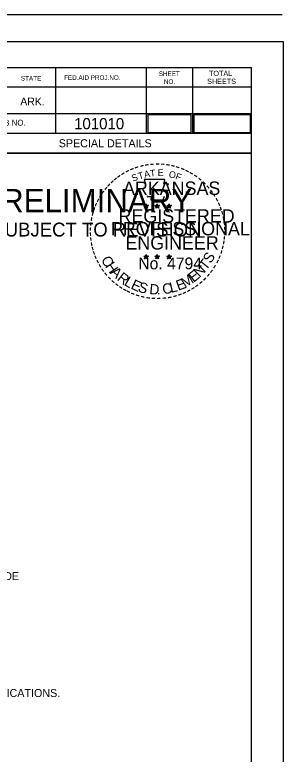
# Model space of a CAD drawing. Extents: x 3575 to 11445, y 9479 to 13278.
# Drawn here: x 5513 to 5714, y 10553 to 11106 of the extents above; entities that cross this region are included whole.
import ezdxf

# ---------------------------------------------------------------- set-up
doc = ezdxf.new("R2010")
doc.units = 0
for name, color, linetype in [('_Drafting 1', 7, 'Continuous'), ('Page Number', 7, 'Continuous'), ('R_NoPlot', 7, 'Continuous'), ('STAMP_PE_CRAFTON-SIGNATURE', 7, 'Continuous'), ('STAMP_PE_FOSTER-SIGNATURE', 7, 'Continuous'), ('STAMP_PE_SEAL-INFO', 7, 'Continuous'), ('STAMP_PE_TAEGTMEYER', 7, 'Continuous'), ('STAMP_PRELIMINARY', 7, 'Continuous'), ('Total_Pages', 7, 'Continuous')]:
    doc.layers.add(name, color=color, linetype=linetype)

msp = doc.modelspace()

# ---------------------------------------------------------------- linework, layer by layer
at = {"layer": '_Drafting 1'}
msp.add_lwpolyline([(4109.53, 11066.7), (4109.53, 10039.4), (5690.43, 10039.4), (5690.43, 11002.7), (5474.93, 11002.7), (5474.93, 11001.26), (5458.74, 11001.26), (5458.74, 11017.3), (5279.13, 11017.3), (5279.13, 11066.7)], close=True, dxfattribs=at)
at = {"layer": 'Page Number'}
msp.add_lwpolyline([(5612.76, 11018.05), (5645.41, 11018.05), (5645.41, 11031.25), (5612.76, 11031.25)], close=True, dxfattribs=at)
at = {"layer": 'R_NoPlot'}
msp.add_lwpolyline([(4047.49, 11086.17), (5714.19, 11086.17), (5714.19, 10019.49), (4047.49, 10019.49)], close=True, dxfattribs=at)
at = {"layer": 'STAMP_PE_FOSTER-SIGNATURE'}
for p, q in [((5609.84, 10963.44), (5611.58, 10962.89)), ((5609.84, 10963.44), (5611.1, 10963.22)), ((5609.84, 10963.44), (5611.02, 10962.83)), ((5610.5, 10961.4), (5611.58, 10962.89)), ((5610.5, 10961.4), (5611.13, 10962.62)), ((5610.5, 10961.4), (5611.57, 10962.49)), ((5611.58, 10964.71), (5611.38, 10963.45)), ((5612.65, 10961.4), (5611.57, 10962.47)), ((5611.58, 10962.89), (5611.58, 10964.71)), ((5611.58, 10964.71), (5611.83, 10963.46)), ((5613.32, 10963.44), (5611.58, 10962.89)), ((5612.65, 10961.4), (5611.58, 10962.89)), ((5613.32, 10963.44), (5611.89, 10963.2)), ((5612.65, 10961.4), (5611.96, 10962.86)), ((5613.32, 10963.44), (5612.3, 10962.93)), ((5618.19, 10963.44), (5619.93, 10962.89)), ((5618.19, 10963.44), (5619.45, 10963.22)), ((5618.19, 10963.44), (5619.37, 10962.83)), ((5618.85, 10961.4), (5619.93, 10962.89)), ((5618.85, 10961.4), (5619.48, 10962.62)), ((5618.85, 10961.4), (5619.92, 10962.49)), ((5619.93, 10964.71), (5619.73, 10963.45)), ((5621, 10961.4), (5619.92, 10962.47)), ((5619.93, 10962.89), (5619.93, 10964.71)), ((5619.93, 10964.71), (5620.18, 10963.46)), ((5621.67, 10963.44), (5619.93, 10962.89)), ((5621, 10961.4), (5619.93, 10962.89)), ((5621.67, 10963.44), (5620.24, 10963.2)), ((5621, 10961.4), (5620.31, 10962.86)), ((5621.67, 10963.44), (5620.65, 10962.93)), ((5627.01, 10963.38), (5628.75, 10962.83)), ((5627.01, 10963.38), (5628.27, 10963.16)), ((5627.01, 10963.38), (5628.19, 10962.77)), ((5627.67, 10961.34), (5628.75, 10962.83)), ((5627.67, 10961.34), (5628.3, 10962.56)), ((5627.67, 10961.34), (5628.74, 10962.43)), ((5628.75, 10964.65), (5628.55, 10963.39)), ((5629.82, 10961.34), (5628.74, 10962.41)), ((5628.75, 10962.83), (5628.75, 10964.65)), ((5628.75, 10964.65), (5629, 10963.4)), ((5630.49, 10963.38), (5628.75, 10962.83)), ((5629.82, 10961.34), (5628.75, 10962.83)), ((5630.49, 10963.38), (5629.06, 10963.14)), ((5629.82, 10961.34), (5629.13, 10962.8)), ((5630.49, 10963.38), (5629.47, 10962.87)), ((5609.82, 10925.58), (5611.56, 10925.02)), ((5609.82, 10925.58), (5611.08, 10925.35)), ((5609.82, 10925.58), (5611, 10924.97)), ((5610.48, 10923.54), (5611.56, 10925.02)), ((5610.48, 10923.54), (5611.11, 10924.76)), ((5610.48, 10923.54), (5611.55, 10924.62)), ((5611.56, 10926.85), (5611.36, 10925.59)), ((5612.63, 10923.54), (5611.55, 10924.61)), ((5611.56, 10925.02), (5611.56, 10926.85)), ((5611.56, 10926.85), (5611.81, 10925.6)), ((5613.3, 10925.58), (5611.56, 10925.02)), ((5612.63, 10923.54), (5611.56, 10925.02)), ((5613.3, 10925.58), (5611.87, 10925.33)), ((5612.63, 10923.54), (5611.94, 10924.99)), ((5613.3, 10925.58), (5612.28, 10925.07)), ((5618.16, 10925.58), (5619.91, 10925.02)), ((5618.16, 10925.58), (5619.43, 10925.35)), ((5618.16, 10925.58), (5619.35, 10924.97)), ((5618.83, 10923.54), (5619.91, 10925.02)), ((5618.83, 10923.54), (5619.46, 10924.76)), ((5618.83, 10923.54), (5619.9, 10924.62)), ((5619.91, 10926.85), (5619.7, 10925.59)), ((5620.97, 10923.54), (5619.9, 10924.61)), ((5619.91, 10925.02), (5619.91, 10926.85)), ((5619.91, 10926.85), (5620.15, 10925.6)), ((5621.64, 10925.58), (5619.91, 10925.02)), ((5620.97, 10923.54), (5619.91, 10925.02)), ((5621.64, 10925.58), (5620.21, 10925.33)), ((5620.97, 10923.54), (5620.29, 10924.99)), ((5621.64, 10925.58), (5620.62, 10925.07)), ((5627, 10925.53), (5628.74, 10924.97)), ((5627, 10925.53), (5628.26, 10925.3)), ((5627, 10925.53), (5628.18, 10924.92)), ((5627.66, 10923.49), (5628.74, 10924.97)), ((5627.66, 10923.49), (5628.29, 10924.71)), ((5627.66, 10923.49), (5628.73, 10924.57)), ((5628.74, 10926.8), (5628.54, 10925.54)), ((5629.81, 10923.49), (5628.73, 10924.56)), ((5628.74, 10924.97), (5628.74, 10926.8)), ((5628.74, 10926.8), (5628.99, 10925.55)), ((5630.48, 10925.53), (5628.74, 10924.97)), ((5629.81, 10923.49), (5628.74, 10924.97)), ((5630.48, 10925.53), (5629.05, 10925.28)), ((5629.81, 10923.49), (5629.12, 10924.94)), ((5630.48, 10925.53), (5629.46, 10925.02))]:
    msp.add_line(p, q, dxfattribs=at)
for points in [[(5610.04, 10982.83), (5611.39, 10978.7)], [(5627.6, 10978.22), (5628.31, 10979.64), (5624.88, 10979.52), (5625.62, 10982.83), (5610.04, 10982.83)], [(5612.5, 10970.72), (5612.5, 10970.28), (5615.32, 10970.19), (5615.05, 10967.82), (5624.4, 10967.82), (5625.4, 10970.5)], [(5611.58, 10964.71), (5612.65, 10961.4), (5609.84, 10963.44), (5613.32, 10963.44), (5610.5, 10961.4), (5611.58, 10964.71)], [(5619.93, 10964.71), (5621, 10961.4), (5618.19, 10963.44), (5621.67, 10963.44), (5618.85, 10961.4), (5619.93, 10964.71)], [(5628.75, 10964.65), (5629.82, 10961.34), (5627.01, 10963.38), (5630.49, 10963.38), (5627.67, 10961.34), (5628.75, 10964.65)], [(5611.56, 10926.85), (5612.63, 10923.54), (5609.82, 10925.58), (5613.3, 10925.58), (5610.48, 10923.54), (5611.56, 10926.85)], [(5619.91, 10926.85), (5620.97, 10923.54), (5618.16, 10925.58), (5621.64, 10925.58), (5618.83, 10923.54), (5619.91, 10926.85)], [(5628.74, 10926.8), (5629.81, 10923.49), (5627, 10925.53), (5630.48, 10925.53), (5627.66, 10923.49), (5628.74, 10926.8)]]:
    msp.add_lwpolyline(points, dxfattribs=at)
for centre, radius in [((5611.58, 10962.88), 0.861), ((5611.58, 10962.88), 0.723), ((5611.58, 10962.88), 0.579), ((5611.58, 10962.88), 0.495), ((5611.58, 10962.88), 0.374), ((5611.58, 10962.88), 0.248), ((5611.58, 10962.88), 0.148), ((5619.93, 10962.88), 0.861), ((5619.93, 10962.88), 0.723), ((5619.93, 10962.88), 0.579), ((5619.93, 10962.88), 0.495), ((5619.93, 10962.88), 0.374), ((5619.93, 10962.88), 0.248), ((5619.93, 10962.88), 0.148), ((5628.75, 10962.82), 0.861), ((5628.75, 10962.82), 0.723), ((5628.75, 10962.82), 0.579), ((5628.75, 10962.82), 0.495), ((5628.75, 10962.82), 0.374), ((5628.75, 10962.82), 0.248), ((5628.75, 10962.82), 0.148), ((5611.56, 10925.02), 0.861), ((5611.56, 10925.02), 0.723), ((5611.56, 10925.02), 0.579), ((5611.56, 10925.02), 0.495), ((5611.56, 10925.02), 0.374), ((5611.56, 10925.02), 0.248), ((5611.56, 10925.02), 0.148), ((5619.9, 10925.02), 0.861), ((5619.9, 10925.02), 0.723), ((5619.9, 10925.02), 0.579), ((5619.9, 10925.02), 0.495), ((5619.9, 10925.02), 0.374), ((5619.9, 10925.02), 0.248), ((5619.9, 10925.02), 0.148), ((5628.74, 10924.97), 0.861), ((5628.74, 10924.97), 0.723), ((5628.74, 10924.97), 0.579), ((5628.74, 10924.97), 0.495), ((5628.74, 10924.97), 0.374), ((5628.74, 10924.97), 0.248), ((5628.74, 10924.97), 0.148)]:
    msp.add_circle(centre, radius, dxfattribs=at)
at = {"layer": 'STAMP_PRELIMINARY'}
for p, q in [((5713.43, 11106.1), (3953.43, 11106.1)), ((4109.53, 11066.7), (5690.43, 11066.7)), ((5543.83, 11066.7), (5543.83, 11017.3)), ((5611.73, 11066.7), (5611.73, 11017.3)), ((5646.43, 11066.7), (5646.43, 11017.3)), ((5690.43, 10039.4), (5690.43, 11066.7)), ((5690.43, 11052), (5474.93, 11052)), ((5690.43, 11052.1), (5690.43, 11052.1)), ((5690.43, 11032), (5474.93, 11032)), ((5690.43, 11017.3), (5279.13, 11017.3)), ((5474.93, 11002.7), (5690.43, 11002.7))]:
    msp.add_line(p, q, dxfattribs=at)
at = {"layer": 'Total_Pages'}
msp.add_lwpolyline([(5647.25, 11018.05), (5689.61, 11018.05), (5689.61, 11031.25), (5647.25, 11031.25)], close=True, dxfattribs=at)

# ---------------------------------------------------------------- texts
at = {"layer": 'STAMP_PE_CRAFTON-SIGNATURE'}
for s, p in [('    BETWEEN THE EXISTING ASPHALT ROADWAY AND THE PROPOSED SUBGRADE', (5195.09, 10683.24)), ('    AS STATED IN SECTION 210, SUBSECTION 210.09, OF THE STANDARD SPECIFICATIONS.', (5195.09, 10595.81))]:
    msp.add_text(s, height=6, dxfattribs=at).set_placement(p)
at = {"layer": 'STAMP_PE_FOSTER-SIGNATURE'}
for s, height, rotation, p in [('-', 8, 5.8968, (5614.57, 10991.03)), ('-', 8, 0.1862, (5618.43, 10991.39)), ('-', 8, 357.743, (5622.04, 10991.33)), ('-', 8, 28.7918, (5597.45, 10985.54)), ('-', 8, 24.3072, (5600.61, 10987.12)), ('-', 8, 19.1761, (5603.78, 10988.47)), ('-', 8, 13.6302, (5607.53, 10989.67)), ('A', 5, 11.2132, (5610.52, 10984.13)), ('-', 8, 10.2193, (5610.92, 10990.48)), ('T', 5, 6.0228, (5614.76, 10984.96)), ('E', 5, 0.8323, (5620.29, 10985.51)), ('-', 8, 352.1617, (5625.76, 10991.05)), ('O', 5, 350.4515, (5628.31, 10984.46)), ('-', 8, 347.2049, (5629.36, 10990.48)), ('-', 8, 342.3362, (5632.53, 10989.7)), ('-', 8, 337.8551, (5636.21, 10988.59)), ('-', 8, 334.1211, (5639.36, 10987.23)), ('-', 8, 38.9507, (5589.19, 10979.82)), ('-', 8, 36.2317, (5591.57, 10981.71)), ('-', 8, 34.0636, (5594.46, 10983.69)), ('S', 5, 21.594, (5601.82, 10981.22)), ('T', 5, 16.4036, (5606.39, 10982.88)), ('F', 5, 340.0707, (5633.08, 10983.32)), ('-', 8, 329.6409, (5642.26, 10985.82)), ('-', 8, 325.8627, (5645.47, 10984.01)), ('-', 8, 320.5297, (5648.52, 10981.88)), ('-', 8, 48.4231, (5584.79, 10975.35)), ('-', 8, 42.9622, (5587.03, 10977.74)), ('-', 8, 315.5786, (5651.52, 10979.44)), ('-', 8, 309.8797, (5654.36, 10976.69)), ('-', 8, 54.2325, (5580.71, 10970.08)), ('-', 8, 50.6142, (5582.77, 10972.92)), ('-', 8, 306.6522, (5656.99, 10973.68)), ('-', 8, 62.8713, (5577.52, 10964.38)), ('-', 8, 58.0706, (5579.08, 10967.45)), ('-', 7, 303.6753, (5659.42, 10970.84)), ('-', 8, 299.6684, (5661.01, 10967.81)), ('-', 8, 72.3945, (5575.13, 10958.17)), ('-', 8, 67.7743, (5576.22, 10961.32)), ('-', 8, 294.6628, (5662.63, 10964.75)), ('-', 8, 290.5728, (5663.92, 10961.86)), ('-', 8, 75.461, (5574.14, 10954.6)), ('-', 8, 285.1233, (5665.09, 10958.96)), ('-', 8, 85.1863, (5573.1, 10947.58)), ('-', 8, 81.2013, (5573.48, 10951.04)), ('-', 8, 280.5493, (5666.09, 10955.25)), ('-', 8, 276.5962, (5666.9, 10951.41)), ('-', 8, 89.0622, (5572.98, 10944.08)), ('-', 8, 274.3301, (5667.2, 10947.8)), ('-', 8, 94.1959, (5573.15, 10940.45)), ('-', 8, 98.9479, (5573.51, 10937.12)), ('-', 8, 263.5172, (5667.27, 10941.31)), ('-', 8, 269.9407, (5667.37, 10944.64)), ('-', 8, 101.7149, (5574.19, 10933.45)), ('-', 8, 260.9953, (5666.92, 10938.04)), ('-', 8, 105.4578, (5575, 10930.48)), ('-', 8, 109.0874, (5576.07, 10927.32)), ('S', 7.7, 57.878, (5660.02, 10919.68)), ('-', 8, 255.7626, (5665.41, 10931.21)), ('-', 8, 255.7626, (5666.37, 10934.65)), ('-', 8, 114.0643, (5577.34, 10924.34)), ('-', 8, 115.7289, (5578.87, 10921.25)), ('C', 7.7, 296.9133, (5577.71, 10923.3)), ('T', 7.7, 51.5114, (5656.38, 10914.47)), ('-', 8, 244.6197, (5663.04, 10924.54)), ('-', 8, 247.8887, (5664.35, 10927.69)), ('-', 8, 120.4471, (5580.65, 10918.32)), ('H', 7.7, 303.2799, (5580.66, 10918.1)), ('N', 7.7, 45.1449, (5651.58, 10909.26)), ('-', 8, 239.0712, (5661.07, 10920.78)), ('-', 8, 125.8934, (5582.67, 10915.52)), ('-', 8, 130.7181, (5584.98, 10912.76)), ('A', 7.7, 316.013, (5584.3, 10912.97)), ('R', 7.7, 322.3796, (5589.43, 10908.06)), ('M', 7.7, 32.4117, (5640.73, 10901.55)), ('E', 7.7, 38.7783, (5647.13, 10905.61)), ('-', 8, 231.2538, (5656.91, 10914.69)), ('-', 8, 233.8452, (5659.06, 10917.52)), ('-', 8, 134.2238, (5587.56, 10910.03)), ('-', 8, 138.9338, (5590.19, 10907.71)), ('L', 7.7, 328.7461, (5594.56, 10904.31)), ('E', 7.7, 335.1127, (5599.59, 10901.52)), ('E', 7.7, 19.6786, (5635.62, 10899.66)), ('-', 8, 221.0851, (5651.9, 10909.32)), ('-', 8, 225.7653, (5654.51, 10911.87)), ('-', 8, 144.6463, (5592.97, 10905.68)), ('-', 8, 148.0898, (5595.77, 10903.83)), ('-', 8, 151.5704, (5598.67, 10902.2)), ('S', 7.7, 341.4792, (5604.92, 10899.36)), ('D', 7.7, 354.2124, (5613.75, 10897.3)), ('C', 7.7, 6.9455, (5624.18, 10897.11)), ('L', 7.7, 13.3121, (5630.1, 10898.06)), ('-', 8, 207.3568, (5643.7, 10903.3)), ('-', 8, 212.2491, (5646.49, 10905.03)), ('-', 8, 215.7363, (5649.16, 10906.96)), ('-', 8, 154.6002, (5601.28, 10900.97)), ('-', 8, 158.5612, (5604.4, 10899.7)), ('-', 8, 162.7983, (5607.83, 10898.63)), ('-', 8, 167.5555, (5611.41, 10897.81)), ('.', 7.7, 0.5789, (5619.62, 10896.92)), ('-', 8, 191.2858, (5630.45, 10898.13)), ('-', 8, 195.4743, (5634.1, 10899.13)), ('-', 8, 200.7184, (5637.48, 10900.34)), ('-', 8, 204.2516, (5640.58, 10901.7)), ('-', 8, 173.1155, (5615.27, 10897.26)), ('-', 8, 176.5183, (5619.01, 10897)), ('-', 8, 181.5918, (5622.73, 10897.09)), ('-', 8, 185.8167, (5626.77, 10897.47))]:
    msp.add_text(s, height=height, rotation=rotation, dxfattribs=at).set_placement(p)
for s, height, p in [('ARKANSAS', 10, (5594.31, 10971.39)), ('REGISTERED', 10, (5590.92, 10950.65)), ('PROFESSIONAL', 10, (5585.18, 10941.13)), ('ENGINEER', 10, (5596.11, 10930.5)), ('No. 4794', 8.785, (5605.74, 10915.75))]:
    msp.add_text(s, height=height, dxfattribs=at).set_placement(p)
at = {"layer": 'STAMP_PE_SEAL-INFO'}
for s, height, p in [('PRELIMINARY', 17.5, (5487.46, 10958.41)), ('SUBJECT TO REVISION', 10.3756, (5496.51, 10940.26))]:
    msp.add_text(s, height=height, dxfattribs=at).set_placement(p)
at = {"layer": 'STAMP_PE_TAEGTMEYER'}
for s, height, p in [('101010', 8.4, (5557.71, 11020.45)), ('SPECIAL DETAILS', 6, (5546.2, 11007))]:
    msp.add_text(s, height=height, dxfattribs=at).set_placement(p)
at = {"layer": 'STAMP_PRELIMINARY'}
for s, height, p in [('SHEET', 3.42, (5621.03, 11060.3)), ('TOTAL', 3.91, (5658.63, 11060.3)), ('STATE', 3.42, (5517.93, 11056.9)), ('FED.AID PROJ.NO.', 3.42, (5550.23, 11057.4)), ('NO.', 3.42, (5624.93, 11054.4)), ('SHEETS', 3.91, (5657.23, 11054.4)), ('ARK.', 5.861, (5517.43, 11038.3)), ('JOB NO.', 4.396, (5497.93, 11023.2))]:
    msp.add_text(s, height=height, dxfattribs=at).set_placement(p)

doc.saveas('drawing.dxf')
